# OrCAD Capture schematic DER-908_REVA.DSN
size Custom; title: DER-908 30 W USB PD with 3.3 V - 21 V / 1.5 A PPS; rev: RevA
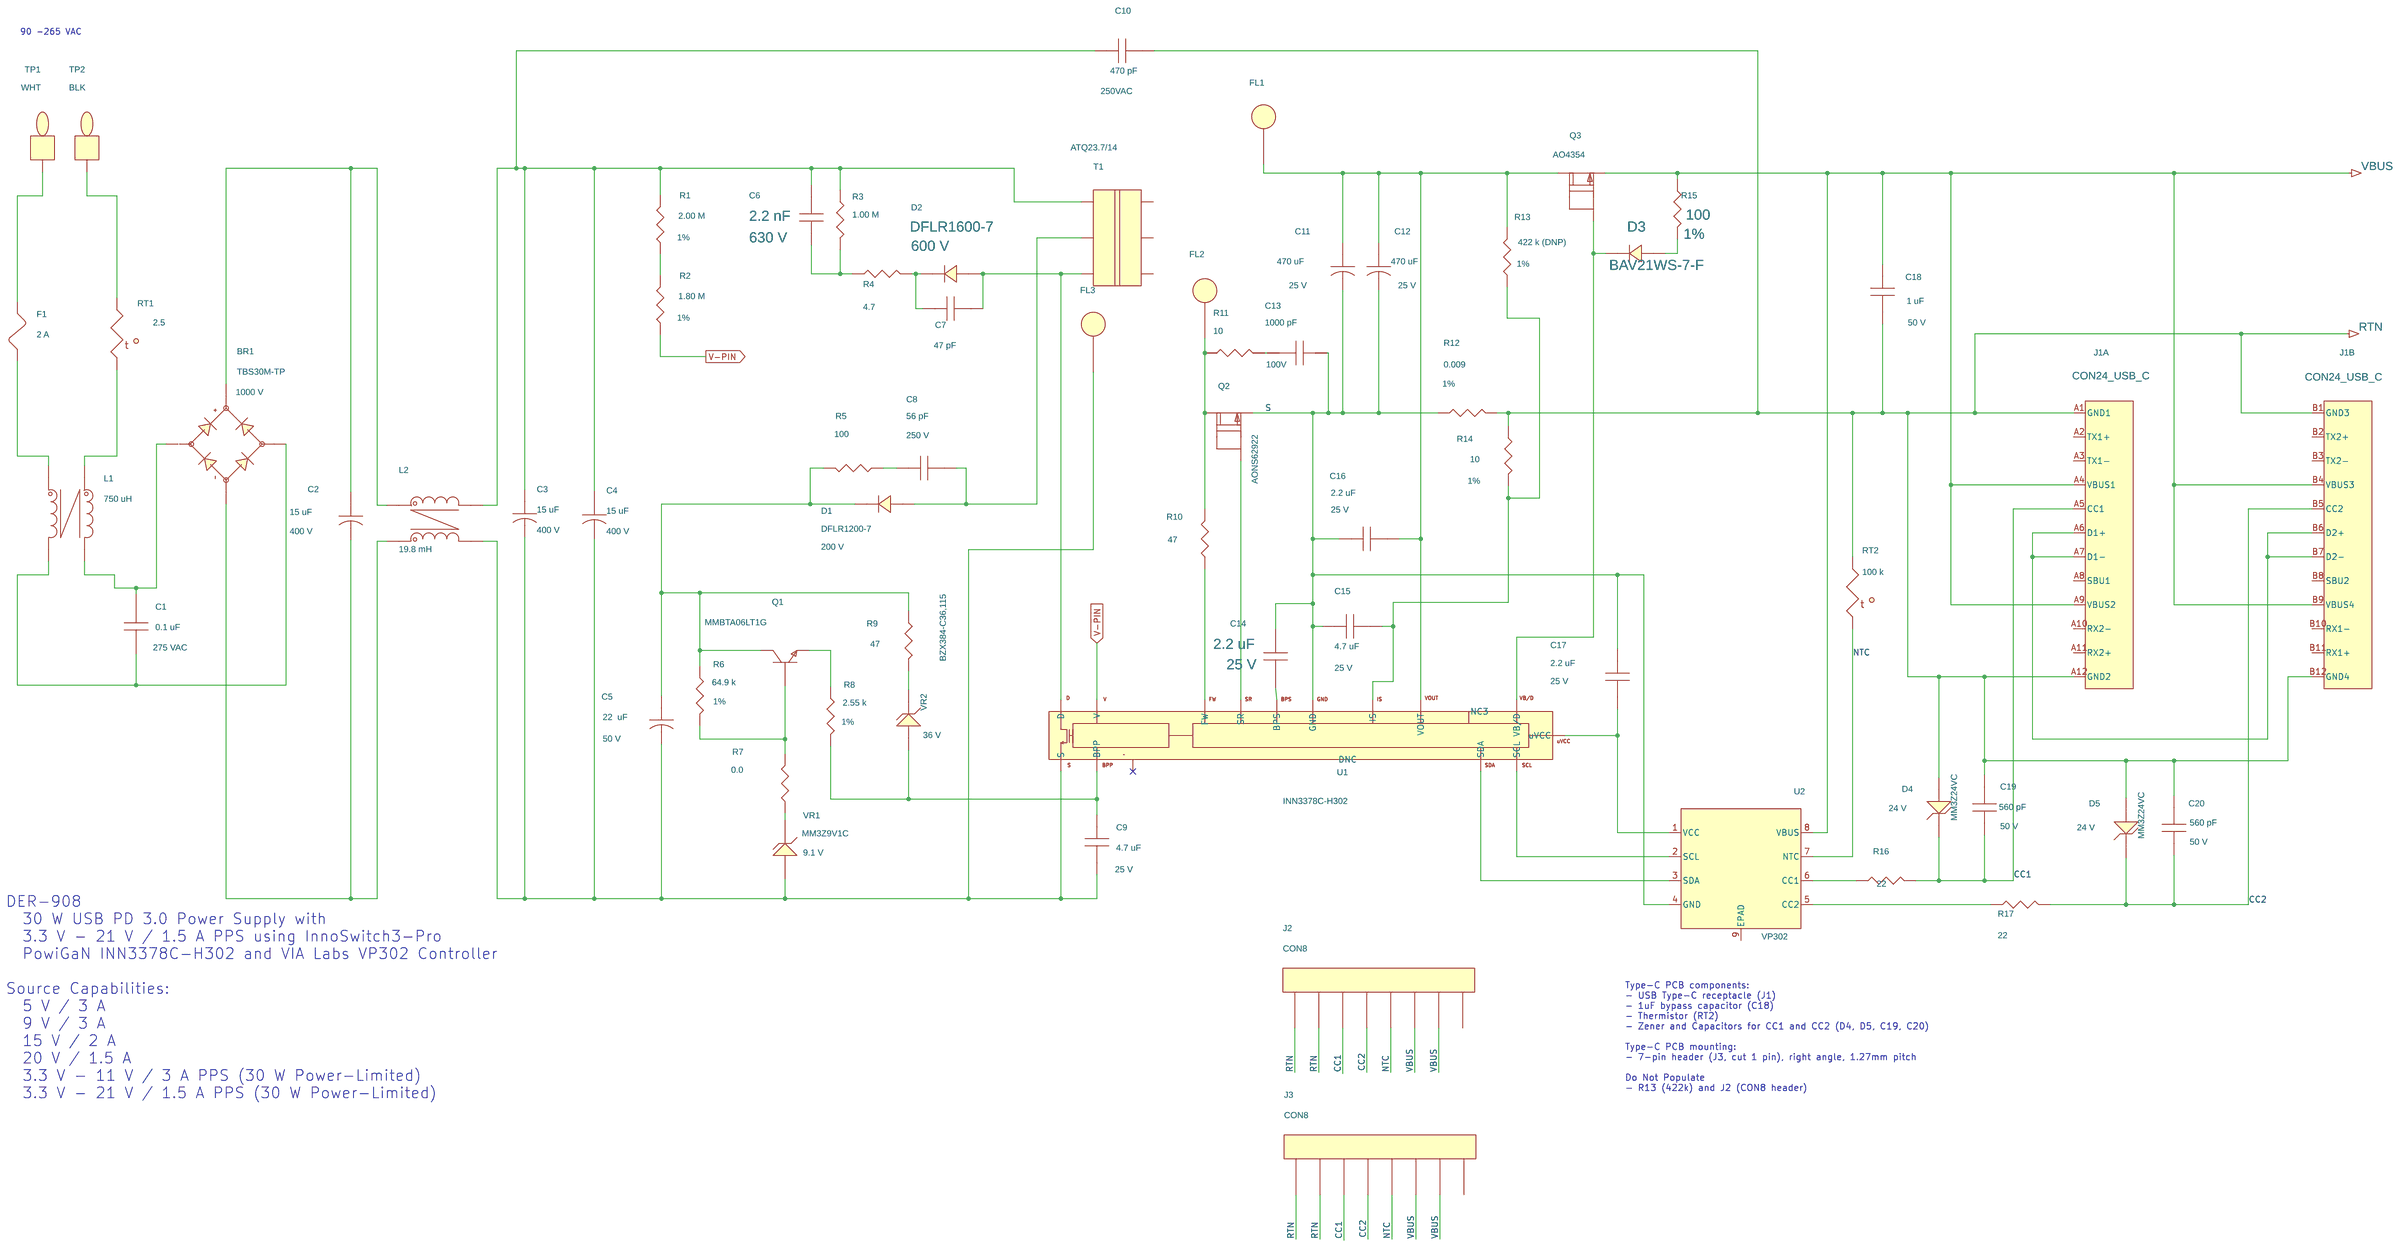
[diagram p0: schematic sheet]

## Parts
BR1  TBS30M-TP  [pismd_4-TBS]
C1  0.1 uF  [pinpxcaprad5x13x11p1mm040]
C2  15 uF  [pipolcapcyld400ls200040]
C3  15 uF  [pipolcapcyld400ls200040]
C4  15 uF  [pipolcapcyld400ls200040]
C5  22  uF  [pipolcapclyd200ls80030]
C6  2.2 nF  [pismc1206]
C7  47 pF  [pismc0805]
C8  56 pF  [pismc0603]
C9  4.7 uF  [pismc0805]
C10  470 pF  [pinpcapraD7mmxLS10mm030]
C11  470 uF  [pipolcapcyld400ls200040]
C12  470 uF  [pipolcapcyld400ls200040]
C13  1000 pF  [pismc0603]
C14  2.2 uF  [pismc0805]
C15  4.7 uF  [pismc0805]
C16  2.2 uF  [pismc0805]
C17  2.2 uF  [pismc0805]
C18  1 uF  [pismc0805]
C19  560 pF  [pismc0603]
C20  560 pF  [pismc0603]
D1  DFLR1200-7  [pismddflr120012]
D2  DFLR1600-7  [pismddflr120012]
D3  BAV21WS-7-F  [pismsod323]
D4  MM3Z24VC  [pismsod323F]
D5  MM3Z24VC  [pismsod323F]
F1  2 A  [pi_rst_microfuse]
FL1  Hole_70mils  [pi_hole_70mil]
FL2  Hole_70mils  [pi_hole_70mil]
FL3  Hole_50mils  [pi_hole_50mil]
J1  CON24_USB_C  [pi_conn_USBC_Wurth]  (sections A,B)
J2  CON8  [pi_hdr_1p27mm_8pin]
J3  CON8  [pi_hdr_1p27mm_8pin]
L1  750 uH  [pi_4p_ls5w4p5xd10p5mmd40]
L2  19.8 mH  [pi_toroid_CMC15x7_12_34V]
Q1  MMBTA06LT1G  [pismsot23123_1]
Q2  AONS62922  [pismpqfn5x6b]
Q3  AO4354  [pismso8]
R1  2.00 M  [pismr1206]
R2  1.80 M  [pismr1206]
R3  1.00 M  [pismr1206]
R4  4.7  [pismr1206]
R5  100  [pismr0402]
R6  64.9 k  [pismr0603]
R7  0.0  [pismr0603]
R8  2.55 k  [pismr0603]
R9  47  [pismr0603]
R10  47  [pismr0402]
R11  10  [pismr0805]
R12  0.009  [pismr0805]
R13  422 k (DNP)  [pismr0603]
R14  10  [pismr0402]
R15  100  [pismr0603]
R16  22  [pismr0402]
R17  22  [pismr0402]
RT1  2.5  [pi_rad150x300ls200d030]
RT2  100 k  [pismr0603]
T1  ATQ23.7/14  [pi_bobbin_ATQ23_7_H_6P]
TP1  WHT  [pitpkeystone100x100]
TP2  BLK  [pitpkeystone100x100]
U1  INN3378C-H302  [pi_ic_insop_24d]
U2  VP302  [PI_SM_DFN-8]
VR1  MM3Z9V1C  [pismsod323F]
VR2  BZX384-C36,115  [pismsod323]

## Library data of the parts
BR1 = DIODE_BRIDGE_+-~~: Disp_Voltage: 1000 V; Part Number: 15-01615-00
C1 = CAP_NP: ALT_SYMBOLS: pinpxcaprad5x13x11p1mm040h; Disp_Voltage: 275 VAC; FPLIST: pinpxcaprad5x13x11p1mm040,pinpxcaprad5x13x11p1mm040h; Part Number: 20-09109-00; Voltage: 275 VAC
C2-C4 = CAP_POL: ALT_SYMBOLS: pipolcapcyld400ls200040800h; Disp_Voltage: 400 V; FPLIST: pipolcapcyld400ls200040,pipolcapcyld400ls200040800h; Part Number: 20-08620-00; Voltage: 400 V
C5 = CAP_POL: ALT_SYMBOLS: pipolcapclyd200ls80030h; Disp_Voltage: 50 V; FPLIST: pipolcapclyd200ls80030,pipolcapclyd200ls80030h; Part Number: 20-00950-00; Voltage: 50 V
C6 = CAP_NP: Disp_Voltage: 630 V; Part Number: 20-08609-00; Voltage: 630 V
C7 = CAP_NP: Disp_Voltage: 1000 V; Part Number: 20-01040-00; Voltage: 1000 V
C8 = CAP_NP: Disp_Voltage: 250 V; Part Number: 20-01325-00; Voltage: 250 V
C9 C15 = CAP_NP: Disp_Voltage: 25 V; Part Number: 20-09137-00; Voltage: 16 V
C10 = CAP_NP: Disp_Voltage: 250VAC; Part Number: 20-01454-00; Voltage: 250VAC
C11 C12 = CAP_POL: Disp_Voltage: 25 V; Part Number: 20-09056-00; Voltage: 25 V
C13 = CAP_NP: Disp_Voltage: 100V; Part Number: 20-09218-00; Voltage: 100V
C14 C16 C17 = CAP_NP: Disp_Voltage: 25 V; Part Number: 20-08603-00; Voltage: 25 V
C18 = CAP_NP: Disp_Voltage: 50 V; Part Number: 20-09146-00; Voltage: 50 V
C19 C20 = CAP_NP: Disp_Voltage: 50 V; Part Number: 20-01450-00; Voltage: 50 V
D1 = DIODE: COMPGROUP: 1; Disp_Voltage: 200 V; Part Number: 15-01019-00
D2 = DIODE: Disp_Voltage: 600 V; Part Number: 15-00826-00
D3 = DIODE: COMPGROUP: 1; Part Number: 15-00385-00
D4 D5 = DIODE_ZENER: Disp_Voltage: 24 V; Part Number: 15-01590-00
F1 = FUSE: ALT_SYMBOLS: pirstmicrofusehoz; FPLIST: pi_rst_microfuse,pirstmicrofusehoz; Part Number: 40-00021-00
FL1 FL2 = FlyingLead: Part Number: 35-00282-00
FL3 = FlyingLead: Part Number: 35-00283-00
J1 = CON24_USB: Part Number: 35-00414-00
J2 J3 = CON8: Part Number: 35-00433-00
L1 = TORRID_4P_12_43a: Part Number: 32-00403-00
L2 = TORRID_4P_12_43a: Part Number: 32-00402-00
Q1 = NPN_BEC: Part Number: 55-00072-00
Q2 = FET_N_SGD_123_4_5678: Part Number: 50-00275-00
Q3 = FET_N_SGD_123_4_5678: Part Number: 50-00260-00
R1 = R: Disp_Tol: 1%; Part Number: 05-03156-00
R2 = R: Disp_Tol: 1%; Part Number: 05-03155-00
R3 = R: Disp_Tol: 1%; Part Number: 05-03149-00
R4 = R: Disp_Tol: 1%; Part Number: 05-06302-00
R5 = R: Part Number: 05-06192-00
R6 = R: Disp_Tol: 1%; Part Number: 05-03262-00
R7 = R: Part Number: 05-03158-00
R8 = R: Disp_Tol: 1%; Part Number: 05-01117-00
R9 = R: ALT_SYMBOLS: pismr0603_1; Part Number: 05-01656-00
R10 = R: Part Number: 05-03426-00
R11 = R: Part Number: 05-01471-00
R12 = R: Disp_Tol: 1%; Part Number: 05-06508-00
R13 = R: Disp_Tol: 1%; Part Number: 05-01234-00
R14 = R: Disp_Tol: 1%; Part Number: 05-05596-00
R15 = R: Disp_Tol: 1%; Part Number: 05-00982-00
R16 R17 = R: COMPGROUP: 1; Part Number: 05-06177-00
RT1 = THERMISTOR: ALT_SYMBOLS: pirad400x300ls200040_h; FPLIST: pi_rad150x300ls200d030,pirad400x300ls200040_h; Part Number: 90-00040-00
RT2 = THERMISTOR: Part Number: 90-00078-00
T1 = BATQ23_7_6P_GENERIC: FPLIST: pi_bobbin_ATQ23_7_H_4P,pi_bobbin_ATQ23_7_H_6P; Part Number: 25-01171-00
TP1 = TESTPOINT: Part Number: 35-00081-00
TP2 = TESTPOINT: Part Number: 35-00079-00
U1 = InnoPro_p15: Part Number: 10-01233-00
U2 = VP302: Part Number: 45-00495-00
VR1 = DIODE_ZENER: Disp_Voltage: 9.1 V; Part Number: 15-01612-00
VR2 = DIODE_ZENER: Disp_Voltage: 36 V; Part Number: 15-01611-00

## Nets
VBUS: C18.1 J1.A4(VBUS1) J1.A9(VBUS2) J1.B4(VBUS3) J1.B9(VBUS4) J2.6 J2.7 J3.6 J3.7 Q3.1(S) R15.2 U2.8(VBUS)
CC1: C19.1 D4.1 J1.A5(CC1) J2.3 J3.3 R16.1
CC2: C20.1 D5.1 J1.B5(CC2) J2.4 J3.4 R17.1
NC3: U1.3(NC3)
NTC: J2.5 J3.5 RT2.2 U2.7(NTC)
RTN: C10.2 C18.2 C19.2 C20.2 D4.2 D5.2 J1.A1(GND1) J1.A12(GND2) J1.B1(GND3) J1.B12(GND4) J2.1 J2.2 J3.1 J3.2 R12.2 R14.1 RT2.1
S: C11.2 C12.2 C13.1 C14.1 C15.1 C16.1 C17.1 Q2.1(S) R12.1 U1.2(GND) U2.4(GND)
V-PIN: R2.1 U1.13(V)
N12237519: F1.2 TP1.1
N12237523: RT1.1 TP2.1
N12237527: BR1.1 C2.1 L2.4
N12237547: C3.1 C4.1 C6.2 C10.1 L2.3 R1.2 R3.1 T1.1
N12237619: F1.1 L1.1
N12237623: L1.4 RT1.2
N12237649: BR1.3 C1.2 L1.3
N12237657: BR1.4 C1.1 L1.2
N12237771: BR1.2 C2.2 L2.1
N12237803: C3.2 C4.2 C5.2 C9.2 FL3.1 L2.2 U1.16(S) VR1.2
N12645578: C5.1 D1.1 Q1.3(COLLECTOR) R5.1 R6.2 R9.2
N12645654: Q1.1(BASE) R6.1 R7.2
N12645698: R7.1 VR1.1
N12646808: Q1.2(EMITTER) R8.2
N12647032: C8.2 D1.2 T1.2
N12647250: C7.2 D2.2 T1.3 U1.24(D)
N12647255: C7.1 D2.1 R4.1
N12647291: C6.1 R3.2 R4.2
N12648519: C8.1 R5.2
N12649378: C9.1 R8.1 U1.14(BPP) VR2.2
N12649481: R9.1 VR2.1
N12651364: R1.1 R2.2
N12652887: C11.1 C12.1 C16.2 FL1.1 Q3.5(D) R13.1 U1.10(VOUT)
N12652989: D3.1 Q3.4(G) U1.8(VB/D)
N12653013: D3.2 R15.1
N12653157: FL2.1 Q2.5(D) R10.1 R11.2
N12653279: Q2.4(G) U1.9(SR)
N12653331: R10.2 U1.11(FW)
N12653381: C15.2 R13.2 R14.2 U1.1(IS)
N12665422: J1.A6(D1+) J1.A7(D1-) J1.B6(D2+) J1.B7(D2-)
N12665660: C17.2 U1.7(uVCC) U2.1(VCC)
N12665712: R16.2 U2.6(CC1)
N12665748: R17.2 U2.5(CC2)
N12666228: U1.5(SCL) U2.2(SCL)
N12666235: U1.6(SDA) U2.3(SDA)
N12666360: C14.2 U1.4(BPS)
N12689323: C13.2 R11.1

Not connected (* = marked no-connect by the designer): J1 A2(TX1+) A3(TX1-) A8(SBU1) A10(RX2-) A11(RX2+) B2(TX2+) B3(TX2-) B8(SBU2) B10(RX1-) B11(RX1+); J2 8; J3 8; Q2 2(S2) 3(S3) 6(D6) 7(D7) 8(D8); Q3 2(S2) 3(S3) 6(D6) 7(D7) 8(D8); T1 4 5 6; U1 12(DNC) 15*; U2 9(EPAD)

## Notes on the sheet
- 90 -265 VAC
- DER-908
    30 W USB PD 3.0 Power Supply with
    3.3 V - 21 V / 1.5 A PPS using InnoSwitch3-Pro
    PowiGaN INN3378C-H302 and VIA Labs VP302 Controller
  Source Capabilities:
    5 V / 3 A
    9 V / 3 A
    15 V / 2 A
    20 V / 1.5 A
    3.3 V - 11 V / 3 A PPS (30 W Power-Limited)
    3.3 V - 21 V / 1.5 A PPS (30 W Power-Limited)
- Type-C PCB components:
  - USB Type-C receptacle (J1)
  - 1uF bypass capacitor (C18)
  - Thermistor (RT2)
  - Zener and Capacitors for CC1 and CC2 (D4, D5, C19, C20)
  Type-C PCB mounting:
  - 7-pin header (J3, cut 1 pin), right angle, 1.27mm pitch
  Do Not Populate
  - R13 (422k) and J2 (CON8 header)
